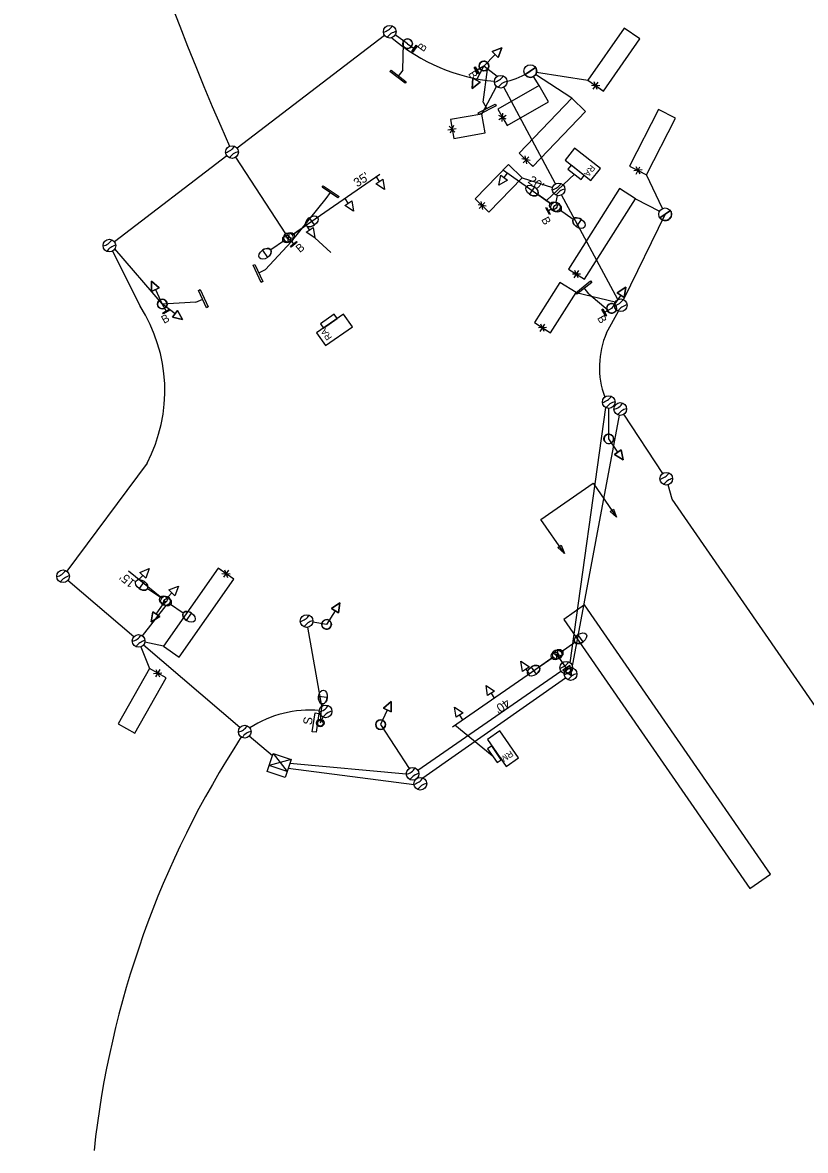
# Model space of a CAD drawing. Extents: x 596176 to 605330, y 332416 to 402398.
# Drawn here: x 602031.8 to 602278.4, y 357338.9 to 357693.9 of the extents above; entities that cross this region are included whole.
import ezdxf

# ---------------------------------------------------------------- set-up
doc = ezdxf.new("R2010")
doc.units = 0
for name, color, linetype in [('P_LTG', 7, 'Continuous'), ('P_SIG', 7, 'Continuous'), ('P_SIG_Bold', 7, 'Continuous'), ('P_SIG_Conduit', 7, 'Continuous'), ('P_SIG_IC', 7, 'Continuous'), ('P_SIG_Loops', 7, 'Continuous')]:
    doc.layers.add(name, color=color, linetype=linetype)

# ---------------------------------------------------------------- blocks, each defined once
blk = doc.blocks.new('_U317')
at = {"layer": 'P_LTG'}
for p, q in [((4.3, 25.1), (-4.1, 25.1)), ((0, 2.3), (0, 18.4))]:
    blk.add_line(p, q, dxfattribs=at)
blk.add_circle((0, 0.1), 3.68, dxfattribs=at)
blk.add_ellipse((0.1, 25.1), major_axis=(0, 6.65), ratio=0.636439, dxfattribs=at)
blk.add_ellipse((0.1, 25.1), major_axis=(0, 6.65), ratio=0.636439, start_param=1.570796, end_param=4.712389, dxfattribs=at)
blk = doc.blocks.new('_U322')
at = {"layer": 'P_LTG'}
for p, q in [((4.3, 25.1), (-4.1, 25.1)), ((0, 2.3), (0, 18.4))]:
    blk.add_line(p, q, dxfattribs=at)
blk.add_circle((0, 0.1), 3.68, dxfattribs=at)
blk.add_ellipse((0.1, 25.1), major_axis=(0, 6.65), ratio=0.636439, dxfattribs=at)
blk.add_ellipse((0.1, 25.1), major_axis=(0, 6.65), ratio=0.636439, start_param=1.570796, end_param=4.712389, dxfattribs=at)
blk = doc.blocks.new('_U225')
at = {"layer": 'P_SIG'}
blk.add_circle((0, 0), 6.1, dxfattribs=at)
for centre, start, end in [((-15.5, 0.1), 336.6741, 22.5272), ((15.5, 0.1), 157.5751, 203.4282)]:
    blk.add_arc(centre, 13.3, start, end, dxfattribs=at)
blk = doc.blocks.new('CONTROL CABINET_8')
at = {"layer": 'P_SIG'}
for p, q in [((-0.229, 0.305), (0.229, 0.305)), ((-0.229, -0.152), (-0.229, 0.305)), ((0.229, 0.305), (0.229, -0.152)), ((-0.229, 0.152), (0.229, 0.152)), ((-0.229, -0.152), (0.229, 0.152)), ((0.229, -0.152), (-0.229, 0.152)), ((0.229, -0.152), (-0.229, -0.152))]:
    blk.add_line(p, q, dxfattribs=at)

msp = doc.modelspace()

# ---------------------------------------------------------------- linework, layer by layer
at = {"layer": 'P_SIG'}
for p, q in [((602151.62, 357678.95), (602151.83, 357687.47)), ((602153.06, 357687.23), (602155.11, 357685.79)), ((602180.65, 357683.85), (602177.11, 357680.24)), ((602151.62, 357678.95), (602150.15, 357677.06)), ((602174.76, 357675.76), (602177.11, 357680.24)), ((602177.11, 357680.24), (602174.99, 357678.92)), ((602176.92, 357668.86), (602178.2, 357679.11)), ((602190.08, 357677.52), (602193.39, 357679.78)), ((602176.92, 357668.86), (602178.02, 357666.72)), ((602183.51, 357645.11), (602184.54, 357646.55)), ((602205.68, 357646.15), (602196.83, 357637.87)), ((602144.22, 357643.87), (602143.25, 357645.35)), ((602116.53, 357625.04), (602127.43, 357638.49)), ((602127.43, 357638.49), (602128.78, 357640.47)), ((602134.38, 357637.07), (602133.41, 357638.55)), ((602198.33, 357635.16), (602197.45, 357634.69)), ((602232.56, 357632.46), (602235.86, 357634.72)), ((602122.22, 357628.65), (602121.25, 357630.13)), ((602108.25, 357616.09), (602116.53, 357625.04)), ((602116.53, 357625.04), (602117.17, 357624.27)), ((602128.92, 357621.52), (602123.84, 357626.17)), ((602108.25, 357616.09), (602106.09, 357615.05)), ((602210.19, 357608.51), (602208.7, 357610.39)), ((602073.65, 357609.87), (602075.81, 357605.3)), ((602086.4, 357605.87), (602088.57, 357606.88)), ((602210.19, 357608.51), (602216.27, 357603.34)), ((602220.2, 357608.13), (602217.35, 357603.96)), ((602075.81, 357605.28), (602077.03, 357603.1)), ((602086.4, 357605.87), (602075.83, 357605.31)), ((602079.86, 357602.24), (602075.83, 357605.31)), ((602217.35, 357603.96), (602215.18, 357602.72)), ((602219.31, 357558.71), (602216.44, 357562.87)), ((602069.64, 357519.92), (602068.43, 357518.63)), ((602078.85, 357514.4), (602077.63, 357513.11)), ((602073.93, 357507.7), (602076.79, 357511.88)), ((602130.22, 357508.77), (602127.55, 357504.47)), ((602203.04, 357490.83), (602200.17, 357495)), ((602190.37, 357490.38), (602191.32, 357488.88)), ((602179.39, 357482.79), (602180.34, 357481.3)), ((602123.05, 357470.68), (602123.93, 357476.62)), ((602123.93, 357476.62), (602125.11, 357476.44)), ((602125.11, 357476.44), (602124.24, 357470.51)), ((602146.67, 357477.53), (602144.56, 357472.93)), ((602169.46, 357475.94), (602170.41, 357474.45)), ((602179.75, 357463.13), (602167.98, 357472.77)), ((602124.24, 357470.51), (602123.05, 357470.68)), ((602108.81, 357458.19), (602110.75, 357463.86)), ((602116.42, 357461.92), (602109.45, 357460.08)), ((602110.75, 357463.86), (602116.42, 357461.92)), ((602110.75, 357463.86), (602115.13, 357458.14)), ((602116.42, 357461.92), (602114.48, 357456.24)), ((602114.48, 357456.24), (602108.81, 357458.19)), ((602115.13, 357458.14), (602109.45, 357460.08))]:
    msp.add_line(p, q, dxfattribs=at)
for points in [[(602154.42, 357684.81), (602155.8, 357686.78), (602156.07, 357686.59), (602154.69, 357684.62)], [(602147.89, 357678.97), (602152.64, 357675.3), (602152.27, 357674.83), (602147.52, 357678.5)], [(602174.36, 357679.94), (602175.62, 357677.9), (602175.35, 357677.73), (602174.08, 357679.77)], [(602175.33, 357665.48), (602180.66, 357668.25), (602180.94, 357667.71), (602175.61, 357664.95)], [(602202.68, 357650.57), (602210.83, 357644.19), (602213.8, 357647.99), (602205.66, 357654.37)], [(602181.81, 357642.69), (602182.44, 357645.87), (602184.59, 357644.35)], [(602207.76, 357644.52), (602208.74, 357645.78), (602204.59, 357649.03), (602203.6, 357647.77)], [(602131.15, 357638.71), (602126.18, 357642.07), (602126.52, 357642.56), (602131.49, 357639.2)], [(602145.84, 357641.4), (602143.12, 357643.15), (602145.33, 357644.59)], [(602136.01, 357634.59), (602133.28, 357636.34), (602135.49, 357637.79)], [(602196.88, 357635.75), (602198.02, 357633.63), (602197.73, 357633.48), (602196.59, 357635.59)], [(602123.84, 357626.17), (602121.12, 357627.93), (602123.32, 357629.37)], [(602116.24, 357623.5), (602118.09, 357625.03), (602118.3, 357624.78), (602116.45, 357623.25)], [(602104.93, 357617.77), (602107.53, 357612.37), (602106.99, 357612.11), (602104.39, 357617.51)], [(602211.1, 357612.12), (602206.4, 357608.39), (602206.03, 357608.86), (602210.73, 357612.59)], [(602089.7, 357604.14), (602087.17, 357609.58), (602087.71, 357609.84), (602090.24, 357604.39)], [(602075.98, 357602.51), (602078.08, 357603.68), (602078.23, 357603.4), (602076.14, 357602.23)], [(602214.59, 357603.77), (602215.77, 357601.68), (602215.49, 357601.52), (602214.3, 357603.61)], [(602132.94, 357602.13), (602124.43, 357596.24), (602127.18, 357592.28), (602135.69, 357598.17)], [(602125.66, 357599.08), (602126.57, 357597.76), (602130.91, 357600.77), (602130, 357602.08)], [(602217.94, 357540.76), (602218.91, 357538.2), (602216.86, 357540.01)], [(602201.5, 357529.38), (602202.46, 357526.82), (602200.41, 357528.63)], [(602071.68, 357522.06), (602070.6, 357519.01), (602068.69, 357520.83)], [(602080.89, 357516.54), (602079.81, 357513.49), (602077.9, 357515.31)], [(602188.78, 357492.87), (602191.48, 357491.08), (602189.26, 357489.67)], [(602177.8, 357485.29), (602180.5, 357483.5), (602178.27, 357482.09)], [(602124.24, 357470.51), (602123.05, 357470.68), (602123.93, 357476.62), (602125.11, 357476.44)], [(602167.87, 357478.44), (602170.57, 357476.65), (602168.35, 357475.23)], [(602178.21, 357468.25), (602184.08, 357459.73), (602188.05, 357462.46), (602182.18, 357470.98)], [(602181.25, 357460.96), (602182.57, 357461.87), (602179.57, 357466.21), (602178.26, 357465.3)]]:
    msp.add_lwpolyline(points, close=True, dxfattribs=at)
for points in [[(602182.72, 357685.97), (602181.6, 357682.93), (602179.71, 357684.77), (602182.72, 357685.97)], [(602181.6, 357682.93), (602182.72, 357685.97), (602179.71, 357684.77), (602181.6, 357682.93)], [(602193.39, 357679.78), (602190.08, 357677.52)], [(602173.39, 357673.14), (602173.6, 357676.37), (602175.93, 357675.15), (602173.39, 357673.14)], [(602173.6, 357676.37), (602173.39, 357673.14), (602175.93, 357675.15), (602173.6, 357676.37)], [(602235.86, 357634.72), (602232.56, 357632.46)], [(602072.38, 357612.55), (602074.84, 357610.44), (602072.46, 357609.31), (602072.38, 357612.55)], [(602074.84, 357610.44), (602072.38, 357612.55), (602072.46, 357609.31), (602074.84, 357610.44)], [(602221.87, 357610.58), (602221.29, 357607.4), (602219.11, 357608.88), (602221.87, 357610.58)], [(602221.29, 357607.4), (602221.87, 357610.58), (602219.11, 357608.88), (602221.29, 357607.4)], [(602082.22, 357600.46), (602079.06, 357601.19), (602080.65, 357603.3), (602082.22, 357600.46)], [(602082.22, 357600.46), (602079.06, 357601.19), (602080.65, 357603.3), (602082.22, 357600.46)], [(602079.06, 357601.19), (602082.22, 357600.46), (602080.65, 357603.3), (602079.06, 357601.19)], [(602221, 357556.28), (602218.23, 357557.96), (602220.4, 357559.46), (602221, 357556.28)], [(602218.23, 357557.96), (602221, 357556.28), (602220.4, 357559.46), (602218.23, 357557.96)], [(602131.78, 357511.29), (602131.34, 357508.08), (602129.1, 357509.46), (602131.78, 357511.29)], [(602131.34, 357508.08), (602131.78, 357511.29), (602129.1, 357509.46), (602131.34, 357508.08)], [(602072.26, 357505.26), (602072.84, 357508.44), (602075.02, 357506.96), (602072.26, 357505.26)], [(602072.26, 357505.26), (602072.84, 357508.44), (602075.02, 357506.96), (602072.26, 357505.26)], [(602072.84, 357508.44), (602072.26, 357505.26), (602075.02, 357506.96), (602072.84, 357508.44)], [(602204.73, 357488.4), (602201.96, 357490.08), (602204.13, 357491.59), (602204.73, 357488.4)], [(602204.73, 357488.4), (602201.96, 357490.08), (602204.13, 357491.59), (602204.73, 357488.4)], [(602201.96, 357490.08), (602204.73, 357488.4), (602204.13, 357491.59), (602201.96, 357490.08)], [(602147.9, 357480.22), (602147.87, 357476.98), (602145.47, 357478.07), (602147.9, 357480.22)], [(602147.87, 357476.98), (602147.9, 357480.22), (602145.47, 357478.07), (602147.87, 357476.98)]]:
    msp.add_lwpolyline(points, dxfattribs=at)
for centre, radius in [((602147.44, 357691.01), 2), ((602153.06, 357687.25), 1.52), ((602177.11, 357680.24), 1.52), ((602177.11, 357680.24), 1.52), ((602177.11, 357680.24), 1.52), ((602177.11, 357680.24), 1.52), ((602177.11, 357680.24), 1.52), ((602177.11, 357680.24), 1.52), ((602191.74, 357678.65), 2), ((602182.41, 357675.3), 2), ((602097.77, 357653.16), 2), ((602200.62, 357641.41), 2), ((602234.21, 357633.59), 2), ((602059.16, 357623.72), 2), ((602075.81, 357605.3), 1.52), ((602075.81, 357605.3), 1.52), ((602075.81, 357605.3), 1.52), ((602220.2, 357604.95), 2), ((602217.35, 357603.96), 1.52), ((602217.35, 357603.96), 1.52), ((602217.35, 357603.96), 1.52), ((602216.42, 357574.46), 2), ((602216.44, 357562.87), 1.52), ((602216.44, 357562.87), 1.52), ((602216.44, 357562.87), 1.52), ((602044.56, 357519.63), 2), ((602121.26, 357505.52), 2), ((602127.55, 357504.47), 1.52), ((602127.55, 357504.47), 1.52), ((602127.55, 357504.47), 1.52), ((602068.35, 357499.28), 2), ((602203.05, 357490.84), 2), ((602127.26, 357477.07), 2), ((602101.8, 357470.71), 2), ((602125.57, 357473.35), 0.9), ((602144.56, 357472.93), 1.52), ((602144.56, 357472.93), 1.52), ((602144.56, 357472.93), 1.52), ((602154.64, 357457.44), 2)]:
    msp.add_circle(centre, radius, dxfattribs=at)
for centre, radius, start, end in [((602144.52, 357695.16), 4.36, 282.2572, 328.1103), ((602150.3, 357686.82), 4.36, 101.3562, 147.2093), ((602153.06, 357687.25), 1.52, 141.2809, 321.2809), ((602153.06, 357687.25), 1.52, 321.2809, 141.2809), ((602177.11, 357680.24), 1.52, 45.745, 225.745), ((602177.11, 357680.24), 1.52, 62.4257, 242.4257), ((602177.11, 357680.24), 1.52, 225.745, 45.745), ((602177.11, 357680.24), 1.52, 242.4257, 62.4257), ((602191.74, 357678.65), 2, 214.3829, 304.6821), ((602191.74, 357678.65), 2, 304.6821, 34.3829), ((602179.49, 357679.44), 4.36, 282.2572, 328.1103), ((602185.27, 357671.11), 4.36, 101.3562, 147.2093), ((602094.85, 357657.31), 4.36, 282.2572, 328.1103), ((602100.63, 357648.97), 4.36, 101.3562, 147.2093), ((602197.69, 357645.55), 4.36, 282.2572, 328.1103), ((602203.47, 357637.22), 4.36, 101.3562, 147.2093), ((602234.21, 357633.59), 2, 214.3829, 304.6821), ((602234.21, 357633.59), 2, 304.6821, 34.3829), ((602056.24, 357627.86), 4.36, 282.2572, 328.1103), ((602062.02, 357619.53), 4.36, 101.3562, 147.2093), ((602075.81, 357605.3), 1.52, 115.4556, 295.4556), ((602075.81, 357605.3), 1.52, 295.4556, 115.4556), ((602217.28, 357609.1), 4.36, 282.2572, 328.1103), ((602217.35, 357603.96), 1.52, 55.8447, 235.8447), ((602217.35, 357603.96), 1.52, 235.8447, 55.8447), ((602223.06, 357600.76), 4.36, 101.3562, 147.2093), ((602213.5, 357578.6), 4.36, 282.2572, 328.1103), ((602219.28, 357570.27), 4.36, 101.3562, 147.2093), ((602216.44, 357562.87), 1.52, 124.7799, 304.7799), ((602216.44, 357562.87), 1.52, 304.7799, 124.7799), ((602041.64, 357523.77), 4.36, 282.2572, 328.1103), ((602047.41, 357515.44), 4.36, 101.3562, 147.2093), ((602118.34, 357509.67), 4.36, 282.2572, 328.1103), ((602124.12, 357501.33), 4.36, 101.3562, 147.2093), ((602127.55, 357504.47), 1.52, 58.2953, 238.2953), ((602127.55, 357504.47), 1.52, 238.2953, 58.2953), ((602065.43, 357503.43), 4.36, 282.2572, 328.1103), ((602071.21, 357495.09), 4.36, 101.3562, 147.2093), ((602200.12, 357494.98), 4.36, 282.2572, 328.1103), ((602205.9, 357486.65), 4.36, 101.3562, 147.2093), ((602124.34, 357481.22), 4.36, 282.2572, 328.1103), ((602130.12, 357472.88), 4.36, 101.3562, 147.2093), ((602098.88, 357474.86), 4.36, 282.2572, 328.1103), ((602144.56, 357472.93), 1.52, 65.4556, 245.4556), ((602144.56, 357472.93), 1.52, 245.4556, 65.4556), ((602104.65, 357466.52), 4.36, 101.3562, 147.2093), ((602151.72, 357461.58), 4.36, 282.2572, 328.1103), ((602157.5, 357453.25), 4.36, 101.3562, 147.2093)]:
    msp.add_arc(centre, radius, start, end, dxfattribs=at)
at = {"layer": 'P_SIG_Bold'}
for p, q in [((602144.36, 357646.12), (602116.81, 357627.06)), ((602183.31, 357647.42), (602198.42, 357636.74)), ((602117.05, 357625.93), (602114.1, 357626.47)), ((602115.31, 357624.73), (602115.84, 357627.68)), ((602065.12, 357521.31), (602075.62, 357512.82)), ((602065.12, 357521.31), (602075.62, 357512.82)), ((602200.44, 357496.47), (602199.9, 357493.52)), ((602167.25, 357472.27), (602198.93, 357494.14)), ((602198.69, 357495.27), (602201.64, 357494.73))]:
    msp.add_line(p, q, dxfattribs=at)
for centre in [(602199.65, 357635.88), (602115.57, 357626.2), (602076.79, 357511.88), (602076.79, 357511.88), (602200.17, 357495)]:
    msp.add_circle(centre, 1.5, dxfattribs=at)
at = {"layer": 'P_SIG_Conduit'}
for p, q in [((602145.84, 357689.82), (602099.36, 357654.38)), ((602153.06, 357687.25), (602149.21, 357690.08)), ((602096.18, 357651.95), (602060.75, 357624.93)), ((602114.75, 357627.46), (602098.96, 357651.55)), ((602199.91, 357637.35), (602200.27, 357639.44)), ((602075.83, 357605.31), (602060.91, 357622.74)), ((602204.29, 357492.4), (602215.48, 357572.7)), ((602066.83, 357500.59), (602046.08, 357518.33)), ((602069.58, 357500.86), (602077.06, 357510.38)), ((602126.05, 357478.7), (602121.62, 357503.56)), ((602100.28, 357472.01), (602069.88, 357497.99)), ((602126.43, 357475.25), (602125.57, 357473.37)), ((602110.48, 357463.08), (602103.18, 357469.27)), ((602152.65, 357457.29), (602116.01, 357460.71))]:
    msp.add_line(p, q, dxfattribs=at)
for points in [[(602181.32, 357676.97), (602177.11, 357680.24)], [(602199.67, 357643.17), (602183.36, 357673.53)], [(602219.26, 357606.71), (602201.56, 357639.65)], [(602234.26, 357633.56), (602221.08, 357606.75)], [(602060.15, 357621.98), (602068.85, 357604.62)], [(602215.75, 357596.29), (602219.51, 357603.08)], [(602216.44, 357562.87), (602216.43, 357572.46)], [(602071.02, 357555.2), (602045.75, 357521.23)], [(602127.55, 357504.47), (602123.24, 357505.2)], [(602201.91, 357492.48), (602200.15, 357494.98)], [(602156.29, 357458.58), (602201.38, 357489.73)], [(602144.56, 357472.93), (602153.55, 357459.12)]]:
    msp.add_lwpolyline(points, dxfattribs=at)
for centre, radius, start, end in [((603007.09, 358054.64), 994, 191.13156, 203.70692), ((602185.58, 357732.59), 57.38, 229.2368, 264.8316), ((602181.12, 357693.33), 18.11, 280.4245, 305.8769), ((602027.19, 357578.04), 49.42, 332.48, 32.5478), ((602240.88, 357585.4), 27.38, 156.5738, 200.0645), ((602122.05, 357443.79), 33.69, 84.499, 123.5425), ((602348.44, 357307.42), 295.8, 146.8807, 173.8922)]:
    msp.add_arc(centre, radius, start, end, dxfattribs=at)
at = {"layer": 'P_SIG_IC'}
for p, q in [((602219.67, 357570.3), (602204.78, 357490.81)), ((602233.47, 357551.97), (602221.15, 357570.6)), ((602157.92, 357456.13), (602202.77, 357487.69)), ((602155.13, 357453.93), (602115.45, 357459.08))]:
    msp.add_line(p, q, dxfattribs=at)
for points in [[(602236.38, 357543.86), (602235.11, 357548.38)], [(602361.01, 357363.75), (602236.38, 357543.86)]]:
    msp.add_lwpolyline(points, dxfattribs=at)
at = {"layer": 'P_SIG_Loops'}
for p, q in [((602204.84, 357670.09), (602193.41, 357677.56)), ((602193.71, 357678.34), (602209.87, 357675.79)), ((602194.5, 357674.14), (602192.78, 357676.95)), ((602213.64, 357674.05), (602211.04, 357674.11)), ((602211.56, 357672.93), (602213.09, 357675.13)), ((602212.82, 357672.85), (602211.85, 357675.24)), ((602212.33, 357674.07), (602214.79, 357672.35)), ((602176.44, 357665.07), (602181.07, 357673.81)), ((602181.79, 357663.39), (602184.11, 357664.72)), ((602184.15, 357663.5), (602181.83, 357664.67)), ((602182.89, 357662.77), (602183.04, 357665.35)), ((602182.97, 357664.08), (602184.46, 357661.48)), ((602165.75, 357660.15), (602168.38, 357660.61)), ((602168, 357659.45), (602166.22, 357661.35)), ((602166.57, 357659.19), (602167.59, 357661.58)), ((602191.66, 357650.51), (602189.11, 357650.99)), ((602189.43, 357649.74), (602191.29, 357651.67)), ((602190.66, 357649.45), (602190.08, 357651.98)), ((602190.37, 357650.74), (602192.53, 357648.66)), ((602226.98, 357647.54), (602224.39, 357647.25)), ((602226.32, 357646.24), (602225.03, 357648.48)), ((602225.06, 357646.15), (602226.28, 357648.54)), ((602225.67, 357647.38), (602228.34, 357646.01)), ((602233.36, 357635.4), (602228.34, 357646.01)), ((602189.12, 357645.02), (602198.71, 357642.01)), ((602224.86, 357638.47), (602232.44, 357634.52)), ((602177.82, 357636.11), (602175.26, 357636.59)), ((602175.58, 357635.34), (602177.44, 357637.27)), ((602176.81, 357635.06), (602176.23, 357637.58)), ((602176.52, 357636.34), (602178.67, 357634.25)), ((602207.59, 357614.77), (602204.99, 357614.72)), ((602205.55, 357613.56), (602206.99, 357615.83)), ((602206.82, 357613.53), (602205.74, 357615.89)), ((602206.27, 357614.73), (602208.81, 357613.13)), ((602206.13, 357608.92), (602218.48, 357605.97)), ((602196.86, 357597.91), (602194.26, 357597.87)), ((602194.82, 357596.71), (602196.26, 357598.97)), ((602196.09, 357596.67), (602195.01, 357599.03)), ((602195.54, 357597.87), (602198.08, 357596.26)), ((602095.9, 357520.43), (602093.45, 357522.16)), ((602096.68, 357521.56), (602095.14, 357519.37)), ((602095.41, 357521.66), (602096.38, 357519.25)), ((602094.59, 357520.46), (602097.19, 357520.38)), ((602069.08, 357497.42), (602071.76, 357490.6)), ((602076.2, 357497.61), (602070.31, 357498.87)), ((602074.37, 357489.13), (602071.76, 357490.6)), ((602075.03, 357490.33), (602073.72, 357488)), ((602073.77, 357490.3), (602074.97, 357488)), ((602073.06, 357489.03), (602075.66, 357489.2))]:
    msp.add_line(p, q, dxfattribs=at)
for points in [[(602214.79, 357672.35), (602226.23, 357688.76), (602221.3, 357692.19), (602209.87, 357675.79)], [(602184.46, 357661.48), (602197.48, 357668.94), (602194.5, 357674.14), (602181.48, 357666.69)], [(602192.52, 357648.62), (602209.16, 357665.93), (602204.84, 357670.09), (602188.2, 357652.78)], [(602167.61, 357657.45), (602177.46, 357659.16), (602176.44, 357665.07), (602166.58, 357663.36)], [(602228.34, 357646.01), (602237.47, 357663.81), (602232.13, 357666.55), (602223, 357648.75)], [(602178.67, 357634.25), (602189.12, 357645.02), (602184.81, 357649.2), (602174.37, 357638.43)], [(602208.81, 357613.13), (602224.86, 357638.47), (602219.79, 357641.68), (602203.74, 357616.34)], [(602198.08, 357596.26), (602206.13, 357608.92), (602201.07, 357612.14), (602193.01, 357599.49)], [(602093.45, 357522.16), (602076.2, 357497.61), (602081.11, 357494.16), (602098.36, 357518.7)], [(602260.86, 357421.34), (602267.44, 357425.89), (602208.83, 357510.59), (602202.25, 357506.04)], [(602071.76, 357490.6), (602061.93, 357473.18), (602067.16, 357470.23), (602076.99, 357487.65)]]:
    msp.add_lwpolyline(points, close=True, dxfattribs=at)
msp.add_lwpolyline([(602202.47, 357526.82), (602195.07, 357537.51), (602211.51, 357548.89), (602218.91, 357538.2)], dxfattribs=at)

# ---------------------------------------------------------------- block references
at = {"layer": 'P_LTG'}
for name, p, xscale, yscale, rotation in [('_U317', (602199.03, 357636.3), 0.32808333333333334, 0.3280833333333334, 55.157402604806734), ('_U317', (602200.26, 357635.45), 0.32808333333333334, 0.3280833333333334, -124.28450284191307), ('_U317', (602116.18, 357626.63), 0.32808333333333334, 0.3280833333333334, -54.75978083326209), ('_U317', (602114.97, 357625.77), 0.3280833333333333, 0.32808333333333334, 124.68212461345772), ('_U317', (602076.15, 357512.27), 0.32808333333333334, 0.3280833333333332, 56.13780507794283), ('_U317', (602077.42, 357511.48), 0.32808333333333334, 0.3280833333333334, -123.86219492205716), ('_U317', (602200.79, 357495.4), 0.32808333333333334, 0.3280833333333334, -54.75978083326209), ('_U317', (602199.56, 357494.56), 0.3280833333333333, 0.32808333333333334, 124.68212461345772), ('_U322', (602125.56, 357473.43), 0.32808333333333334, 0.3280833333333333, -5.710972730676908)]:
    msp.add_blockref(name, p, dxfattribs=dict(at, xscale=xscale, yscale=yscale, rotation=rotation))
at = {"layer": 'P_SIG_Bold', "xscale": 13.123333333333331, "yscale": 13.12333333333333, "rotation": 161.13235822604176}
msp.add_blockref('CONTROL CABINET_8', (602112.94, 357461), dxfattribs=at)
at = {"layer": 'P_SIG_IC', "xscale": 0.3280833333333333, "yscale": 0.32808333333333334, "rotation": 124.68212461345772}
for p in [(602220.05, 357572.27), (602234.57, 357550.31), (602204.41, 357488.84), (602157.09, 357454.32)]:
    msp.add_blockref('_U225', p, dxfattribs=at)

# ---------------------------------------------------------------- texts
at = {"layer": 'P_SIG'}
for s, height, rotation, p in [('B', 2.52, 55.0066, (602158.06, 357684.52)), ('B', 2.52, 301.8126, (602172.07, 357677.81)), ('RA', 2, 231.9334, (602210.79, 357649.31)), ('B', 2.52, 298.3138, (602195.11, 357631.94)), ('B', 2.52, 39.5715, (602119.14, 357621.35)), ('B', 2.52, 29.1813, (602076.38, 357599.04)), ('B', 2.52, 299.5276, (602212.72, 357600.9)), ('RA', 2, 124.6821, (602129.34, 357594.77)), ('S', 2.8, 81.5767, (602122.87, 357472.68)), ('RM', 2, 214.5631, (602185.5, 357464.9))]:
    msp.add_text(s, height=height, rotation=rotation, dxfattribs=at).set_placement(p)
at = {"layer": 'P_SIG_Bold'}
for s, rotation, p in [("35'", 33.5503, (602137.23, 357641.98)), ("20'", 324.7609, (602190.75, 357643.65)), ("15'", 141.0458, (602067.55, 357517.91)), ("40'", 214.5939, (602184.18, 357481.24))]:
    msp.add_text(s, height=2.8, rotation=rotation, dxfattribs=at).set_placement(p)

doc.saveas('drawing.dxf')
